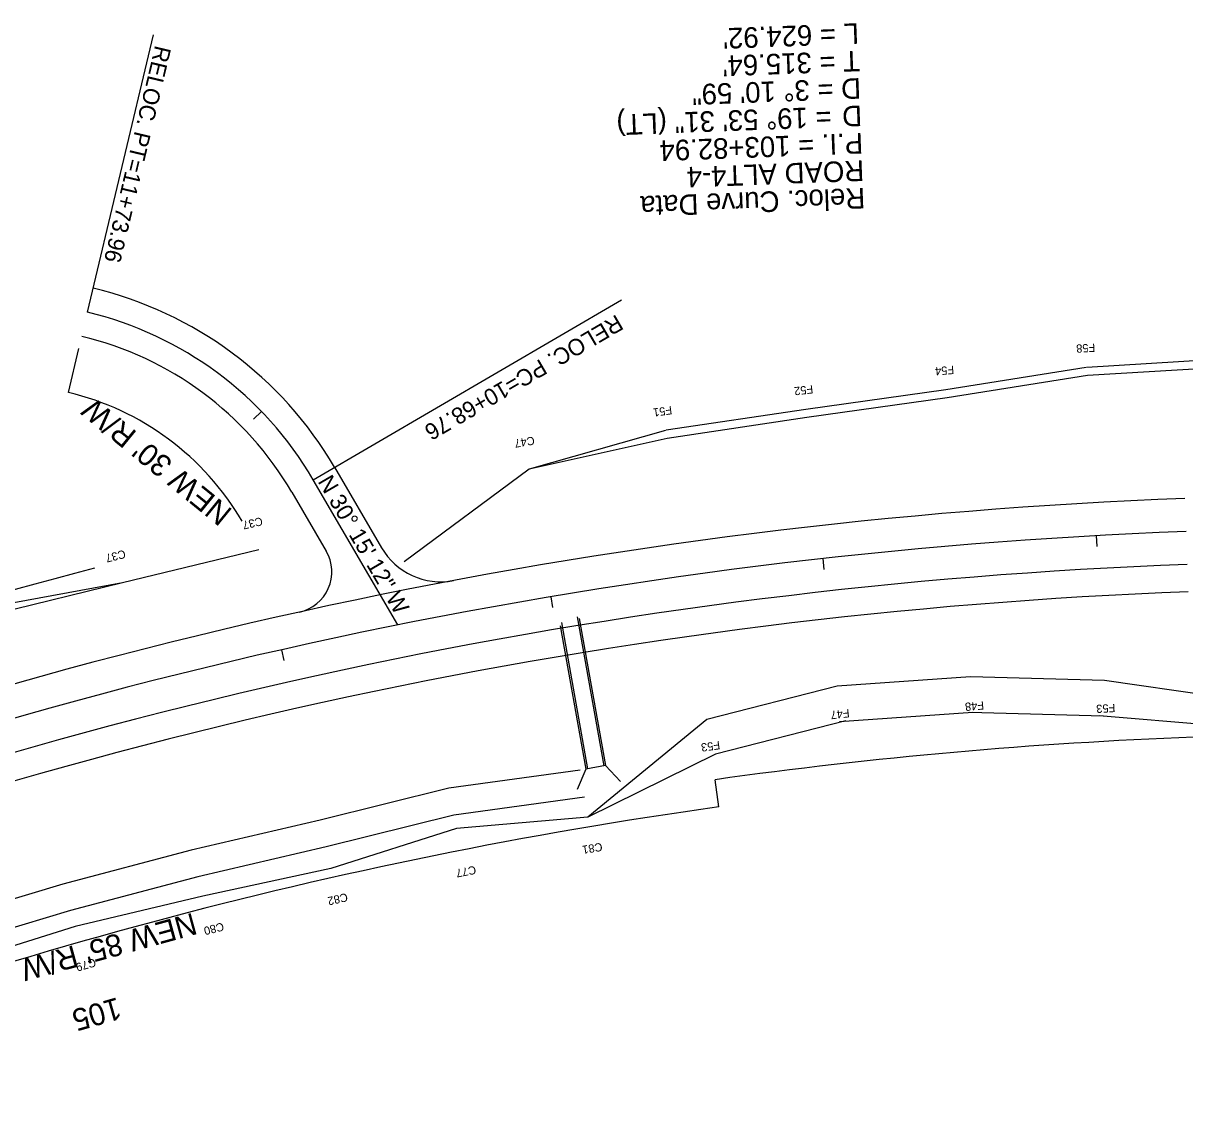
# Model space of a CAD drawing. Extents: x 1475170 to 1480100, y 1103245 to 1119475.
# Drawn here: x 1476354 to 1476777, y 1111085.8 to 1111480.1 of the extents above; entities that cross this region are included whole.
import ezdxf

# ---------------------------------------------------------------- set-up
doc = ezdxf.new("R2010")
doc.units = 0
for name, color, linetype in [('RD_HC_CL_Rel', 7, 'Continuous'), ('RD_HC_Data_Rel', 7, 'Continuous'), ('RD_HC_Data_Tic_Rel', 7, 'Continuous'), ('RD_HC_TX_Rel_Sta50', 7, 'Continuous'), ('RD_HY_Area_Clvt', 7, 'Continuous'), ('RD_PD_CstnLmt', 7, 'Continuous'), ('RD_PD_CstnLmt_TX', 7, 'Continuous'), ('RD_PD_DR_Ditch', 7, 'Continuous'), ('RD_PD_DR_ErosCtrl', 7, 'Continuous'), ('RD_PD_Final_TrvlWay', 7, 'Continuous'), ('RD_PD_GR', 7, 'Continuous'), ('RD_PD_RW', 7, 'Continuous'), ('RD_PD_RW_TX', 7, 'Continuous')]:
    doc.layers.add(name, color=color, linetype=linetype)

msp = doc.modelspace()

# ---------------------------------------------------------------- linework, layer by layer
at = {"layer": 'RD_HC_CL_Rel'}
msp.add_line((1476490.46, 1111260.95), (1476459.61, 1111313.85), dxfattribs=at)
for centre, radius, start, end in [((1476347.32, 1111248.35), 130, 30.2532, 76.6174), ((1476845.33, 1109496.28), 1800, 92.16, 112.05197)]:
    msp.add_arc(centre, radius, start, end, dxfattribs=at)
at = {"layer": 'RD_HC_Data_Rel'}
for p, q in [((1476377.4, 1111374.82), (1476401.45, 1111475.87)), ((1476459.61, 1111313.85), (1476571.91, 1111379.34))]:
    msp.add_line(p, q, dxfattribs=at)
at = {"layer": 'RD_HC_Data_Tic_Rel'}
for p, q in [((1476440.8, 1111338.69), (1476437.92, 1111335.91)), ((1476744.82, 1111293.47), (1476745.05, 1111289.48)), ((1476645.19, 1111285.12), (1476645.63, 1111281.14)), ((1476546.17, 1111271.24), (1476546.83, 1111267.3)), ((1476448.07, 1111251.89), (1476448.95, 1111247.99))]:
    msp.add_line(p, q, dxfattribs=at)
at = {"layer": 'RD_HY_Area_Clvt'}
for p, q in [((1476555.73, 1111263.94), (1476565.46, 1111209.62)), ((1476556.54, 1111263.25), (1476566.12, 1111209.73)), ((1476549.55, 1111260.6), (1476558.9, 1111208.44)), ((1476550.01, 1111261.84), (1476559.56, 1111208.56)), ((1476558.9, 1111208.44), (1476555.79, 1111201.07)), ((1476566.12, 1111209.73), (1476558.9, 1111208.44)), ((1476571.59, 1111203.9), (1476566.12, 1111209.73))]:
    msp.add_line(p, q, dxfattribs=at)
at = {"layer": 'RD_PD_CstnLmt'}
for p, q in [((1476741.56, 1111351.77), (1476690.45, 1111343.63)), ((1476792.54, 1111354.86), (1476741.56, 1111351.77)), ((1476690.45, 1111343.63), (1476639.44, 1111336.51)), ((1476639.44, 1111336.51), (1476588.57, 1111328.88)), ((1476588.57, 1111328.88), (1476538.33, 1111317.72)), ((1476538.33, 1111317.72), (1476492.7, 1111283.97)), ((1476439.84, 1111288.25), (1476390.22, 1111276.33)), ((1476390.22, 1111276.33), (1476340.61, 1111264.19)), ((1476698.96, 1111242.06), (1476650.39, 1111238.62)), ((1476747.77, 1111240.68), (1476698.96, 1111242.06)), ((1476650.39, 1111238.62), (1476602.92, 1111226.49)), ((1476797.11, 1111233.59), (1476747.77, 1111240.68)), ((1476602.92, 1111226.49), (1476559.69, 1111190.97)), ((1476559.69, 1111190.97), (1476511.86, 1111186.81)), ((1476511.86, 1111186.81), (1476466.08, 1111172.29)), ((1476466.08, 1111172.29), (1476419.4, 1111162.21)), ((1476419.4, 1111162.21), (1476372.91, 1111151.08)), ((1476372.91, 1111151.08), (1476327.28, 1111136.83))]:
    msp.add_line(p, q, dxfattribs=at)
at = {"layer": 'RD_PD_DR_Ditch'}
for p, q in [((1476556.81, 1111208.07), (1476508.96, 1111201.5)), ((1476508.96, 1111201.5), (1476462.1, 1111189.9)), ((1476558.47, 1111198.21), (1476510.9, 1111191.69)), ((1476510.9, 1111191.69), (1476464.3, 1111180.14)), ((1476462.1, 1111189.9), (1476415.13, 1111178.89)), ((1476415.13, 1111178.89), (1476368.48, 1111166.58)), ((1476464.3, 1111180.14), (1476417.61, 1111169.2)), ((1476368.48, 1111166.58), (1476322.26, 1111152.73)), ((1476417.61, 1111169.2), (1476371.23, 1111156.97)), ((1476371.23, 1111156.97), (1476325.27, 1111143.19))]:
    msp.add_line(p, q, dxfattribs=at)
at = {"layer": 'RD_PD_DR_ErosCtrl'}
for p, q in [((1476792.36, 1111357.86), (1476741.38, 1111354.77)), ((1476741.09, 1111354.73), (1476689.98, 1111346.59)), ((1476690.03, 1111346.6), (1476639.02, 1111339.48)), ((1476638.99, 1111339.48), (1476588.13, 1111331.85)), ((1476587.92, 1111331.81), (1476538.33, 1111317.72)), ((1476390.22, 1111276.33), (1476339.9, 1111267.11)), ((1476699.88, 1111229.09), (1476651.31, 1111225.65)), ((1476747.41, 1111227.69), (1476698.6, 1111229.06)), ((1476653.61, 1111226.02), (1476606.14, 1111213.89)), ((1476797.47, 1111223.6), (1476745.92, 1111227.82)), ((1476606.14, 1111213.89), (1476559.69, 1111190.97))]:
    msp.add_line(p, q, dxfattribs=at)
at = {"layer": 'RD_PD_Final_TrvlWay'}
for p, q in [((1476467.39, 1111318.38), (1476484.47, 1111289.08)), ((1476451.84, 1111309.31), (1476464.35, 1111287.86))]:
    msp.add_line(p, q, dxfattribs=at)
for centre, radius, start, end in [((1476347.32, 1111248.35), 139, 30.2532, 76.6174), ((1476347.32, 1111248.35), 121, 30.2532, 76.6174), ((1476845.33, 1109496.28), 1812, 92.16, 112.05197), ((1476451.39, 1111280.3), 15, 282.4519, 30.2532), ((1476506.07, 1111301.68), 25, 210.2532, 280.6426), ((1476845.33, 1109496.28), 1788, 92.16, 112.05197)]:
    msp.add_arc(centre, radius, start, end, dxfattribs=at)
at = {"layer": 'RD_PD_GR'}
msp.add_arc((1476845.33, 1109496.28), 1778, 92.16, 112.05197, dxfattribs=at)
at = {"layer": 'RD_PD_RW'}
for p, q in [((1476370.46, 1111345.63), (1476374.27, 1111361.65)), ((1476607.37, 1111194.69), (1476605.99, 1111204.59))]:
    msp.add_line(p, q, dxfattribs=at)
for centre, radius, start, end in [((1476347.32, 1111248.35), 100, 30.2285, 76.6174), ((1476845.33, 1109496.28), 1845, 104.60849, 112.05197), ((1476845.33, 1109496.28), 1725, 92.16, 97.97556), ((1476845.33, 1109496.28), 1715, 97.97556, 112.05197)]:
    msp.add_arc(centre, radius, start, end, dxfattribs=at)

# ---------------------------------------------------------------- texts
at = {"layer": 'RD_HC_Data_Rel'}
for s, height, rotation, p in [("L = 624.92'", 7.5, 182.16, (1476658.23, 1111480.15)), ('RELOC. PT=11+73.96', 6, 256.6174, (1476402.1, 1111472.31)), ("T = 315.64'", 7.5, 182.16, (1476658.61, 1111470.15)), ('D = 3%%d 10\' 59"', 7.5, 182.16, (1476658.99, 1111460.16)), ('    = 19%%d 53\' 31" (LT)', 7.5, 182.16, (1476659.37, 1111450.17)), ('D', 7.5, 182.16, (1476659.37, 1111450.17)), ('P.I. = 103+82.94', 7.5, 182.16, (1476659.74, 1111440.18)), ('ROAD ALT4-4', 7.5, 182.16, (1476660.12, 1111430.18)), ('Reloc. Curve Data', 7.5, 182.16, (1476660.5, 1111420.19)), ('RELOC. PC=10+68.76', 6, 210.2532, (1476570.1, 1111374.21)), ('N 30%%d 15\' 12" W', 6, 300.2532, (1476461.13, 1111313.23))]:
    msp.add_text(s, height=height, rotation=rotation, dxfattribs=at).set_placement(p)
at = {"layer": 'RD_HC_TX_Rel_Sta50'}
msp.add_text('105', height=8, rotation=195.9333, dxfattribs=at).set_placement((1476388.33, 1111125.41))
at = {"layer": 'RD_PD_CstnLmt_TX'}
for s, rotation, p in [('F58', 183.2009, (1476744.34, 1111363.45)), ('F54', 184.7925, (1476692.9, 1111355.37)), ('F52', 186.384, (1476641.53, 1111348.31)), ('F51', 187.9756, (1476590.09, 1111340.71)), ('C47', 189.5671, (1476539.99, 1111329.66)), ('C37', 192.7502, (1476440.84, 1111300.26)), ('C37', 194.3418, (1476390.88, 1111288.37)), ('F48', 184.7925, (1476703.79, 1111233.16)), ('F47', 186.384, (1476654.77, 1111230.33)), ('F53', 183.2009, (1476751.64, 1111232.23)), ('F53', 187.9756, (1476607.56, 1111218.69)), ('C81', 189.5671, (1476564.68, 1111181.67)), ('C77', 191.1587, (1476518.61, 1111173.3)), ('C82', 192.7502, (1476471.82, 1111163.34)), ('C80', 194.3418, (1476426.67, 1111152.65)), ('C79', 195.9333, (1476379.99, 1111139.58))]:
    msp.add_text(s, height=3, rotation=rotation, dxfattribs=at).set_placement(p)
at = {"layer": 'RD_PD_RW_TX'}
for s, rotation, p in [("NEW 30' R/W", 140.8578, (1476430.58, 1111302.71)), ("NEW 85' R/W", 195.3182, (1476415.83, 1111156.22))]:
    msp.add_text(s, height=8, rotation=rotation, dxfattribs=at).set_placement(p)

doc.saveas('drawing.dxf')
